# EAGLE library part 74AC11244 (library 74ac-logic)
Octal BUFFER/DRIVER
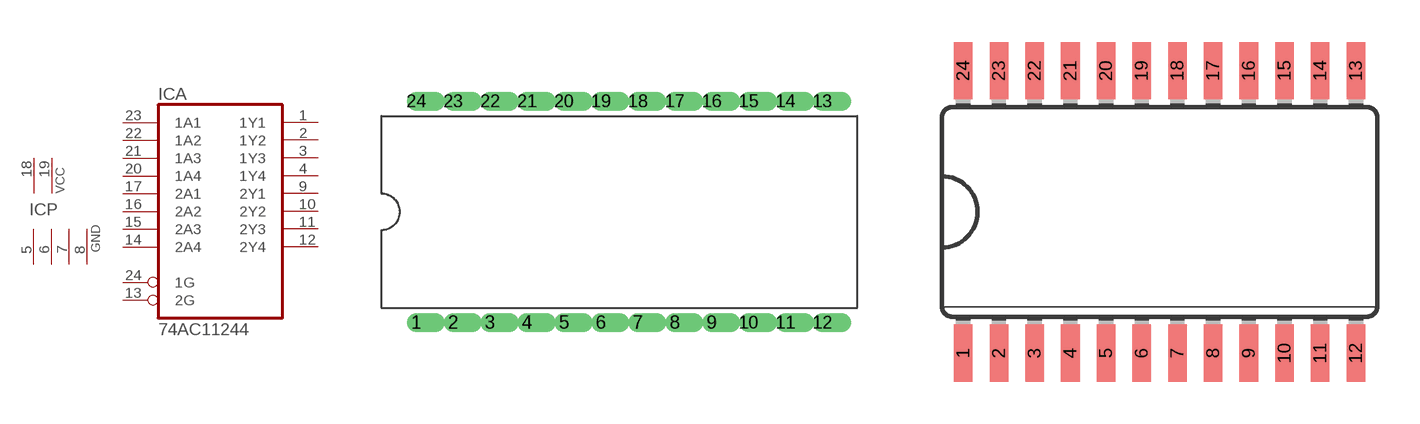
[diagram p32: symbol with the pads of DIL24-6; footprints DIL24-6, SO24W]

Designator prefix IC; gates A=7411244 P=2PWR4GND

## 74AC11244  [DIL24-6]
1  A:1Y1  hiz
2  A:1Y2  hiz
3  A:1Y3  hiz
4  A:1Y4  hiz
5  P:GND  pwr
6  P:GND  pwr
7  P:GND  pwr
8  P:GND  pwr
9  A:2Y1  hiz
10  A:2Y2  hiz
11  A:2Y3  hiz
12  A:2Y4  hiz
13  A:2G  in
14  A:2A4  in
15  A:2A3  in
16  A:2A2  in
17  A:2A1  in
18  P:VCC  pwr
19  P:VCC  pwr
20  A:1A4  in
21  A:1A3  in
22  A:1A2  in
23  A:1A1  in
24  A:1G  in

## 74AC11244D  [SO24W]
Pads as for DIL24-6

## Footprint DIL24-6 (pad centres in mm)
Dual In Line 0.6 inch
drill 0.813 offset: 1 -13.97,-7.62; 2 -11.43,-7.62; 3 -8.89,-7.62; 4 -6.35,-7.62; 5 -3.81,-7.62; 6 -1.27,-7.62; 7 1.27,-7.62; 8 3.81,-7.62; 9 6.35,-7.62; 10 8.89,-7.62; 11 11.43,-7.62; 12 13.97,-7.62; 13 13.97,7.62; 14 11.43,7.62; 15 8.89,7.62; 16 6.35,7.62; 17 3.81,7.62; 18 1.27,7.62; 19 -1.27,7.62; 20 -3.81,7.62; 21 -6.35,7.62; 22 -8.89,7.62; 23 -11.43,7.62; 24 -13.97,7.62

## Footprint SO24W (pad centres in mm)
Wide Small Outline package 300 mil
smd 0.66 x 2.032: 1 -6.985,-5.029; 2 -5.715,-5.029; 3 -4.445,-5.029; 4 -3.175,-5.029; 5 -1.905,-5.029; 6 -0.635,-5.029; 7 0.635,-5.029; 8 1.905,-5.029; 9 3.175,-5.029; 10 4.445,-5.029; 11 5.715,-5.029; 12 6.985,-5.029; 13 6.985,5.029; 14 5.715,5.029; 15 4.445,5.029; 16 3.175,5.029; 17 1.905,5.029; 18 0.635,5.029; 19 -0.635,5.029; 20 -1.905,5.029; 21 -3.175,5.029; 22 -4.445,5.029; 23 -5.715,5.029; 24 -6.985,5.029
